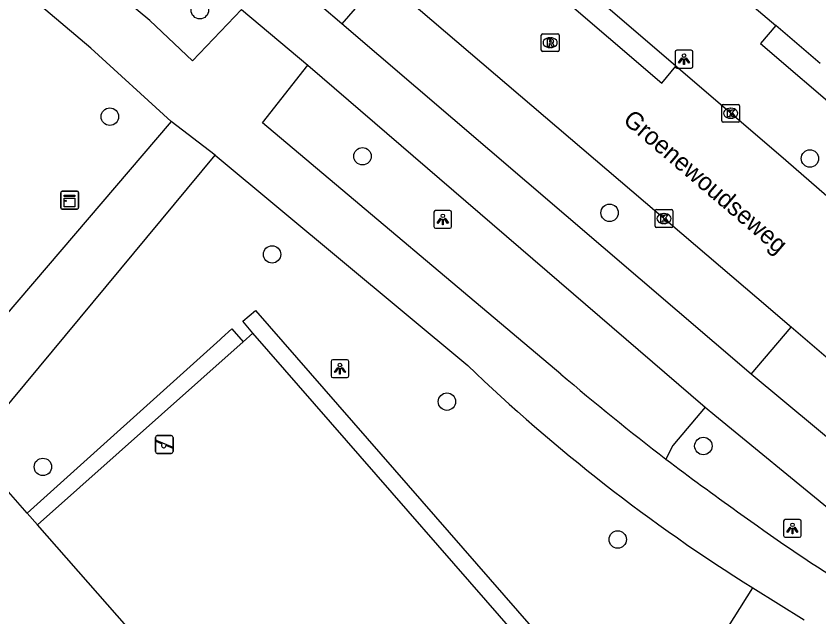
# Model space of a CAD drawing. Extents: x 159280 to 160375, y 384531 to 385872.
# Drawn here: x 159841.11 to 159886.24, y 384692.69 to 384726.45 of the extents above; entities that cross this region are included whole.
import ezdxf

# ---------------------------------------------------------------- set-up
doc = ezdxf.new("R2010")
doc.units = 0
for name, color, linetype in [('IMGEO_Boom', 7, 'Continuous'), ('IMGEO_Fietspad_open', 7, 'Continuous'), ('IMGEO_Groenvoorziening', 7, 'Continuous'), ('IMGEO_Haag', 7, 'Continuous'), ('IMGEO_Kast', 7, 'Continuous'), ('IMGEO_Kolk', 7, 'Continuous'), ('IMGEO_Lichtpunt', 7, 'Continuous'), ('IMGEO_Openbare_ruimte_label', 7, 'Continuous'), ('IMGEO_Pand', 7, 'Continuous'), ('IMGEO_Rijbaan_lokaal_open', 7, 'Continuous'), ('IMGEO_Rioolput', 7, 'Continuous'), ('IMGEO_Speelvoorziening', 7, 'Continuous'), ('IMGEO_Voetpad_halfverhard', 7, 'Continuous'), ('IMGEO_Voetpad_open', 7, 'Continuous')]:
    doc.layers.add(name, color=color, linetype=linetype)

msp = doc.modelspace()

# ---------------------------------------------------------------- linework, layer by layer
at = {"layer": 'IMGEO_Boom'}
for centre in [(159851.438, 384726.777), (159846.38, 384720.795), (159860.58, 384718.569), (159885.726, 384718.444), (159874.466, 384715.393), (159855.499, 384713.057), (159865.326, 384704.785), (159879.739, 384702.293), (159842.615, 384701.121), (159874.925, 384697.04)]:
    msp.add_circle(centre, 0.489, dxfattribs=at)
at = {"layer": 'IMGEO_Fietspad_open'}
for points in [[(159859.416, 384726.013), (159855.982, 384728.954)], [(159853.776, 384726.823), (159857.499, 384723.68)], [(159882.433, 384706.327), (159859.416, 384726.013)], [(159857.499, 384723.68), (159879.839, 384704.467)], [(159887.991, 384701.708), (159882.433, 384706.327)], [(159879.839, 384704.467), (159880.391, 384704.016), (159886.924, 384698.671), (159891.005, 384695.574), (159895.266, 384692.85)]]:
    msp.add_lwpolyline(points, dxfattribs=at)
at = {"layer": 'IMGEO_Groenvoorziening'}
msp.add_lwpolyline([(159853.87, 384708.147), (159854.423, 384708.639)], dxfattribs=at)
at = {"layer": 'IMGEO_Haag'}
for points in [[(159854.423, 384708.639), (159853.849, 384709.311), (159854.572, 384709.914), (159874.803, 384686.719), (159874.093, 384686.089), (159873.538, 384686.724)], [(159841.741, 384698.514), (159852.586, 384708.276), (159852.664, 384708.346), (159853.242, 384708.868), (159853.87, 384708.147)], [(159873.538, 384686.724), (159854.423, 384708.639)], [(159842.315, 384697.861), (159853.87, 384708.147)], [(159879.839, 384704.467), (159878.018, 384702.312), (159877.637, 384701.562)]]:
    msp.add_lwpolyline(points, dxfattribs=at)
at = {"layer": 'IMGEO_Kast'}
for p, q in [((159843.619, 384715.678), (159843.619, 384716.519)), ((159843.619, 384716.519), (159843.619, 384715.678)), ((159843.694, 384716.603), (159844.535, 384716.603)), ((159844.535, 384716.603), (159843.694, 384716.603)), ((159844.619, 384716.528), (159844.619, 384715.687)), ((159844.619, 384715.687), (159844.619, 384716.528)), ((159844.544, 384715.603), (159843.703, 384715.603)), ((159843.703, 384715.603), (159844.544, 384715.603))]:
    msp.add_line(p, q, dxfattribs=at)
for points in [[(159843.814, 384716.393), (159844.414, 384716.393), (159844.414, 384716.308), (159843.814, 384716.308), (159843.814, 384716.393)], [(159843.814, 384716.218), (159844.414, 384716.218), (159844.414, 384715.729), (159843.814, 384715.729), (159843.814, 384716.218)]]:
    msp.add_lwpolyline(points, dxfattribs=at)
msp.add_circle((159843.898, 384716.067), 0.0377, dxfattribs=at)
for centre, start, end in [((159843.697, 384716.525), 92.4484, 184.2845), ((159843.697, 384716.525), 92.4484, 184.2845), ((159844.541, 384716.525), 2.4484, 94.2845), ((159844.541, 384716.525), 2.4484, 94.2845), ((159843.697, 384715.681), 182.4484, 274.2845), ((159843.697, 384715.681), 182.4484, 274.2845), ((159844.541, 384715.681), 272.4484, 4.2845), ((159844.541, 384715.681), 272.4484, 4.2845)]:
    msp.add_arc(centre, 0.0779, start, end, dxfattribs=at)
at = {"layer": 'IMGEO_Kolk'}
for p, q in [((159880.774, 384720.558), (159880.774, 384721.41)), ((159880.849, 384721.484), (159881.701, 384721.484)), ((159881.775, 384721.41), (159881.775, 384720.558)), ((159881.262, 384721.264), (159881.287, 384721.264)), ((159881.701, 384720.484), (159880.849, 384720.484)), ((159881.285, 384720.704), (159881.26, 384720.704)), ((159877.021, 384714.645), (159877.021, 384715.497)), ((159877.096, 384715.571), (159877.948, 384715.571)), ((159878.022, 384715.497), (159878.022, 384714.645)), ((159877.509, 384715.351), (159877.534, 384715.351)), ((159877.948, 384714.571), (159877.096, 384714.571)), ((159877.532, 384714.791), (159877.507, 384714.791))]:
    msp.add_line(p, q, dxfattribs=at)
for points in [[(159880.774, 384720.558), (159880.774, 384721.41)], [(159880.849, 384721.484), (159881.701, 384721.484)], [(159881.775, 384721.41), (159881.775, 384720.558)], [(159881.095, 384721.184), (159881.218, 384721.184), (159881.218, 384721.033), (159881.348, 384721.184), (159881.512, 384721.184), (159881.366, 384721.033), (159881.519, 384720.784), (159881.367, 384720.784), (159881.282, 384720.948), (159881.218, 384720.881), (159881.218, 384720.784), (159881.095, 384720.784), (159881.095, 384721.184)], [(159881.701, 384720.484), (159880.849, 384720.484)], [(159877.021, 384714.645), (159877.021, 384715.497)], [(159877.096, 384715.571), (159877.948, 384715.571)], [(159878.022, 384715.497), (159878.022, 384714.645)], [(159877.342, 384715.271), (159877.465, 384715.271), (159877.465, 384715.12), (159877.595, 384715.271), (159877.759, 384715.271), (159877.613, 384715.12), (159877.766, 384714.871), (159877.614, 384714.871), (159877.529, 384715.035), (159877.465, 384714.968), (159877.465, 384714.871), (159877.342, 384714.871), (159877.342, 384715.271)], [(159877.948, 384714.571), (159877.096, 384714.571)]]:
    msp.add_lwpolyline(points, dxfattribs=at)
for centre, start, end in [((159880.851, 384721.408), 91.552, 178.448), ((159880.851, 384721.408), 91.552, 178.448), ((159881.699, 384721.408), 1.552, 88.448), ((159881.699, 384721.408), 1.552, 88.448), ((159880.851, 384720.56), 181.552, 268.448), ((159880.851, 384720.56), 181.552, 268.448), ((159881.699, 384720.56), 271.552, 358.448), ((159881.699, 384720.56), 271.552, 358.448), ((159877.098, 384715.495), 91.552, 178.448), ((159877.098, 384715.495), 91.552, 178.448), ((159877.946, 384715.495), 1.552, 88.448), ((159877.946, 384715.495), 1.552, 88.448), ((159877.098, 384714.647), 181.552, 268.448), ((159877.098, 384714.647), 181.552, 268.448), ((159877.946, 384714.647), 271.552, 358.448), ((159877.946, 384714.647), 271.552, 358.448)]:
    msp.add_arc(centre, 0.0765, start, end, dxfattribs=at)
for centre, major_axis, ratio, start_param, end_param in [((159881.261, 384720.984), (-0.387, 0.002), 0.722429, 4.712389, 7.853982), ((159881.286, 384720.984), (-0.39, 0.002), 0.717154, 1.570796, 4.712389), ((159877.508, 384715.071), (-0.387, 0.002), 0.722429, 4.712389, 7.853982), ((159877.533, 384715.071), (-0.39, 0.002), 0.717154, 1.570796, 4.712389)]:
    msp.add_ellipse(centre, major_axis=major_axis, ratio=ratio, start_param=start_param, end_param=end_param, dxfattribs=at)
at = {"layer": 'IMGEO_Lichtpunt'}
for p, q in [((159879.057, 384724.523), (159878.249, 384724.523)), ((159879.057, 384724.523), (159878.249, 384724.523)), ((159878.155, 384724.428), (159878.155, 384723.621)), ((159878.155, 384724.428), (159878.155, 384723.621)), ((159879.151, 384723.621), (159879.151, 384724.428)), ((159879.151, 384723.621), (159879.151, 384724.428)), ((159878.249, 384723.527), (159879.057, 384723.527)), ((159878.249, 384723.527), (159879.057, 384723.527)), ((159865.497, 384715.519), (159864.689, 384715.519)), ((159865.497, 384715.519), (159864.689, 384715.519)), ((159864.595, 384715.424), (159864.595, 384714.617)), ((159864.595, 384715.424), (159864.595, 384714.617)), ((159865.591, 384714.617), (159865.591, 384715.424)), ((159865.591, 384714.617), (159865.591, 384715.424)), ((159864.689, 384714.523), (159865.497, 384714.523)), ((159864.689, 384714.523), (159865.497, 384714.523)), ((159858.811, 384707.041), (159858.811, 384706.234)), ((159858.811, 384707.041), (159858.811, 384706.234)), ((159859.713, 384707.136), (159858.905, 384707.136)), ((159859.713, 384707.136), (159858.905, 384707.136)), ((159859.807, 384706.234), (159859.807, 384707.041)), ((159859.807, 384706.234), (159859.807, 384707.041)), ((159858.905, 384706.14), (159859.713, 384706.14)), ((159858.905, 384706.14), (159859.713, 384706.14)), ((159884.247, 384698.069), (159884.247, 384697.262)), ((159884.247, 384698.069), (159884.247, 384697.262)), ((159885.149, 384698.164), (159884.341, 384698.164)), ((159885.149, 384698.164), (159884.341, 384698.164)), ((159885.243, 384697.262), (159885.243, 384698.069)), ((159885.243, 384697.262), (159885.243, 384698.069)), ((159884.341, 384697.168), (159885.149, 384697.168)), ((159884.341, 384697.168), (159885.149, 384697.168))]:
    msp.add_line(p, q, dxfattribs=at)
for points in [[(159878.529, 384724.092), (159878.568, 384724.064), (159878.38, 384723.802), (159878.342, 384723.829), (159878.529, 384724.092)], [(159878.631, 384724.044), (159878.678, 384724.044), (159878.678, 384723.722), (159878.631, 384723.722), (159878.631, 384724.044)], [(159878.741, 384724.064), (159878.779, 384724.091), (159878.966, 384723.829), (159878.927, 384723.801), (159878.741, 384724.064)], [(159864.969, 384715.088), (159865.008, 384715.06), (159864.82, 384714.798), (159864.782, 384714.825), (159864.969, 384715.088)], [(159865.071, 384715.04), (159865.118, 384715.04), (159865.118, 384714.718), (159865.071, 384714.718), (159865.071, 384715.04)], [(159865.181, 384715.06), (159865.219, 384715.087), (159865.406, 384714.825), (159865.367, 384714.797), (159865.181, 384715.06)], [(159859.185, 384706.705), (159859.224, 384706.677), (159859.036, 384706.415), (159858.998, 384706.442), (159859.185, 384706.705)], [(159859.287, 384706.657), (159859.334, 384706.657), (159859.334, 384706.335), (159859.287, 384706.335), (159859.287, 384706.657)], [(159859.397, 384706.677), (159859.435, 384706.704), (159859.622, 384706.442), (159859.583, 384706.414), (159859.397, 384706.677)], [(159884.621, 384697.733), (159884.66, 384697.705), (159884.472, 384697.443), (159884.434, 384697.47), (159884.621, 384697.733)], [(159884.723, 384697.685), (159884.77, 384697.685), (159884.77, 384697.363), (159884.723, 384697.363), (159884.723, 384697.685)], [(159884.833, 384697.705), (159884.871, 384697.732), (159885.058, 384697.47), (159885.019, 384697.442), (159884.833, 384697.705)]]:
    msp.add_lwpolyline(points, dxfattribs=at)
for centre in [(159878.654, 384724.226), (159865.094, 384715.222), (159859.31, 384706.839), (159884.746, 384697.867)]:
    msp.add_circle(centre, 0.0994, dxfattribs=at)
for centre, start, end in [((159878.249, 384724.428), 90, 180), ((159878.249, 384724.428), 90, 180), ((159879.057, 384724.428), 0, 90), ((159879.057, 384724.428), 0, 90), ((159878.249, 384723.621), 180, 270), ((159878.249, 384723.621), 180, 270), ((159879.057, 384723.621), 270, 0), ((159879.057, 384723.621), 270, 360), ((159864.689, 384715.424), 90, 180), ((159864.689, 384715.424), 90, 180), ((159865.497, 384715.424), 0, 90), ((159865.497, 384715.424), 0, 90), ((159864.689, 384714.617), 180, 270), ((159864.689, 384714.617), 180, 270), ((159865.497, 384714.617), 270, 0), ((159865.497, 384714.617), 270, 360), ((159858.905, 384707.041), 90, 180), ((159858.905, 384707.041), 90, 180), ((159859.713, 384707.041), 0, 90), ((159859.713, 384707.041), 0, 90), ((159858.905, 384706.234), 180, 270), ((159858.905, 384706.234), 180, 270), ((159859.713, 384706.234), 270, 0), ((159859.713, 384706.234), 270, 360), ((159884.341, 384698.069), 90, 180), ((159884.341, 384698.069), 90, 180), ((159885.149, 384698.069), 0, 90), ((159885.149, 384698.069), 0, 90), ((159884.341, 384697.262), 180, 270), ((159884.341, 384697.262), 180, 270), ((159885.149, 384697.262), 270, 0), ((159885.149, 384697.262), 270, 360)]:
    msp.add_arc(centre, 0.0946, start, end, dxfattribs=at)
at = {"layer": 'IMGEO_Pand'}
for points in [[(159881.618, 384727.795), (159883.819, 384725.91)], [(159886.312, 384723.774), (159883.819, 384725.91)]]:
    msp.add_lwpolyline(points, dxfattribs=at)
at = {"layer": 'IMGEO_Rijbaan_lokaal_open'}
for points in [[(159878.198, 384723.622), (159866.219, 384733.909), (159858.974, 384740.138), (159853.929, 384744.456)], [(159868.281, 384730.496), (159877.401, 384722.674), (159878.198, 384723.622)], [(159884.673, 384708.967), (159884.588, 384709.04), (159883.518, 384709.956), (159861.667, 384728.607)], [(159905.572, 384700.855), (159904.969, 384701.213), (159903.358, 384702.353), (159902.164, 384703.1), (159900.173, 384704.762), (159898.864, 384705.788), (159891.993, 384711.699), (159884.369, 384718.326), (159878.198, 384723.622)], [(159890.184, 384704.251), (159884.673, 384708.967)]]:
    msp.add_lwpolyline(points, dxfattribs=at)
at = {"layer": 'IMGEO_Rioolput'}
for p, q in [((159870.629, 384724.525), (159870.629, 384725.377)), ((159870.704, 384725.451), (159871.556, 384725.451)), ((159871.63, 384725.377), (159871.63, 384724.525)), ((159871.117, 384725.231), (159871.142, 384725.231)), ((159871.556, 384724.451), (159870.704, 384724.451)), ((159871.14, 384724.671), (159871.115, 384724.671))]:
    msp.add_line(p, q, dxfattribs=at)
for points in [[(159870.629, 384724.525), (159870.629, 384725.377)], [(159870.704, 384725.451), (159871.556, 384725.451)], [(159871.63, 384725.377), (159871.63, 384724.525)], [(159871.218, 384725.149), (159870.966, 384725.151), (159870.966, 384724.751)], [(159870.966, 384724.751), (159871.09, 384724.751), (159871.09, 384724.913), (159871.101, 384724.913)], [(159871.144, 384725.07), (159871.09, 384725.07), (159871.09, 384724.989)], [(159871.09, 384724.989), (159871.142, 384724.989)], [(159871.556, 384724.451), (159870.704, 384724.451)], [(159871.148, 384724.884), (159871.219, 384724.751), (159871.359, 384724.751), (159871.294, 384724.877)]]:
    msp.add_lwpolyline(points, dxfattribs=at)
for centre, radius, start, end in [((159870.706, 384725.375), 0.0765, 91.552, 178.448), ((159870.706, 384725.375), 0.0765, 91.552, 178.448), ((159871.554, 384725.375), 0.0765, 1.552, 88.448), ((159871.554, 384725.375), 0.0765, 1.552, 88.448), ((159871.1, 384724.86), 0.0533, 26.0293, 88.6989), ((159871.126, 384725.178), 0.19, 274.7715, 282.9687), ((159871.15, 384724.974), 0.0964, 77.0061, 93.1865), ((159871.164, 384725.031), 0.0378, 276.6634, 79.6772), ((159871.217, 384725.039), 0.109, 350.3612, 89.416), ((159871.215, 384725.039), 0.112, 277.5842, 350.9817), ((159871.199, 384724.824), 0.108, 29.5134, 73.7905), ((159870.706, 384724.527), 0.0765, 181.552, 268.448), ((159870.706, 384724.527), 0.0765, 181.552, 268.448), ((159871.554, 384724.527), 0.0765, 271.552, 358.448), ((159871.554, 384724.527), 0.0765, 271.552, 358.448)]:
    msp.add_arc(centre, radius, start, end, dxfattribs=at)
for centre, major_axis, ratio, start_param, end_param in [((159871.116, 384724.951), (-0.387, 0.002), 0.722429, 4.712389, 7.853982), ((159871.141, 384724.951), (-0.39, 0.002), 0.717154, 1.570796, 4.712389)]:
    msp.add_ellipse(centre, major_axis=major_axis, ratio=ratio, start_param=start_param, end_param=end_param, dxfattribs=at)
at = {"layer": 'IMGEO_Speelvoorziening'}
for p, q in [((159849.043, 384702.876), (159849.833, 384702.876)), ((159849.833, 384702.876), (159849.043, 384702.876)), ((159848.943, 384701.976), (159848.943, 384702.776)), ((159848.943, 384702.776), (159848.943, 384701.976)), ((159849.326, 384702.404), (159848.987, 384702.541)), ((159849.012, 384702.601), (159849.888, 384702.248)), ((159849.933, 384702.776), (159849.933, 384701.976)), ((159849.933, 384701.976), (159849.933, 384702.776)), ((159849.864, 384702.188), (159849.524, 384702.325)), ((159849.833, 384701.876), (159849.043, 384701.876)), ((159849.043, 384701.876), (159849.833, 384701.876))]:
    msp.add_line(p, q, dxfattribs=at)
for centre, radius, start, end in [((159849.043, 384702.776), 0.1, 90, 180), ((159849.043, 384702.776), 0.1, 90, 180), ((159849.833, 384702.776), 0.1, 0, 90), ((159849.833, 384702.776), 0.1, 360, 90), ((159849, 384702.571), 0.0327, 68.078, 248.078), ((159849.405, 384702.314), 0.12, 130.9928, 5.1632), ((159849.043, 384701.976), 0.1, 180, 270), ((159849.043, 384701.976), 0.1, 180, 270), ((159849.833, 384701.976), 0.1, 270, 0), ((159849.833, 384701.976), 0.1, 270, 0), ((159849.876, 384702.218), 0.0327, 248.078, 68.078)]:
    msp.add_arc(centre, radius, start, end, dxfattribs=at)
at = {"layer": 'IMGEO_Voetpad_halfverhard'}
for points in [[(159853.776, 384726.823), (159851.029, 384723.93), (159848.632, 384726.205), (159825.6, 384745.284), (159805.116, 384763.503), (159800.659, 384767.301), (159801.703, 384771.392)], [(159849.834, 384720.526), (159845.317, 384724.65), (159823.259, 384743.264), (159802.05, 384761.39), (159798.105, 384764.665)], [(159871.726, 384706.336), (159854.968, 384720.449), (159857.499, 384723.68)], [(159849.834, 384720.526), (159826.424, 384693.169), (159820.737, 384699.345)], [(159852.296, 384718.633), (159849.834, 384720.526)], [(159841.741, 384698.514), (159838.571, 384702.123), (159852.296, 384718.633)], [(159852.296, 384718.633), (159866.495, 384706.815)], [(159842.315, 384697.861), (159841.741, 384698.514)], [(159861.434, 384676.096), (159842.315, 384697.861)], [(159869.522, 384673.668), (159882.522, 384694.32)], [(159882.522, 384694.32), (159885.403, 384692.531)]]:
    msp.add_lwpolyline(points, dxfattribs=at)
for centre, radius, start, end in [((159934.876, 384777.999), 98.707, 226.15063, 237.96785), ((159961.459, 384811.394), 138.163, 229.49839, 232.64969), ((159963.048, 384813.547), 140.84, 232.66719, 234.70196), ((159946.59, 384787.793), 110.32, 233.94935, 241.49163)]:
    msp.add_arc(centre, radius, start, end, dxfattribs=at)
at = {"layer": 'IMGEO_Voetpad_open'}
for points in [[(159861.667, 384728.607), (159859.416, 384726.013)], [(159883.819, 384725.91), (159882.951, 384724.896), (159887.762, 384720.776), (159888.63, 384721.789)], [(159882.433, 384706.327), (159884.673, 384708.967)]]:
    msp.add_lwpolyline(points, dxfattribs=at)

# ---------------------------------------------------------------- texts
at = {"layer": 'IMGEO_Openbare_ruimte_label'}
msp.add_text('Groenewoudseweg', height=1, rotation=319.5416, dxfattribs=at).set_placement((159875.162, 384720.507))

doc.saveas('drawing.dxf')
